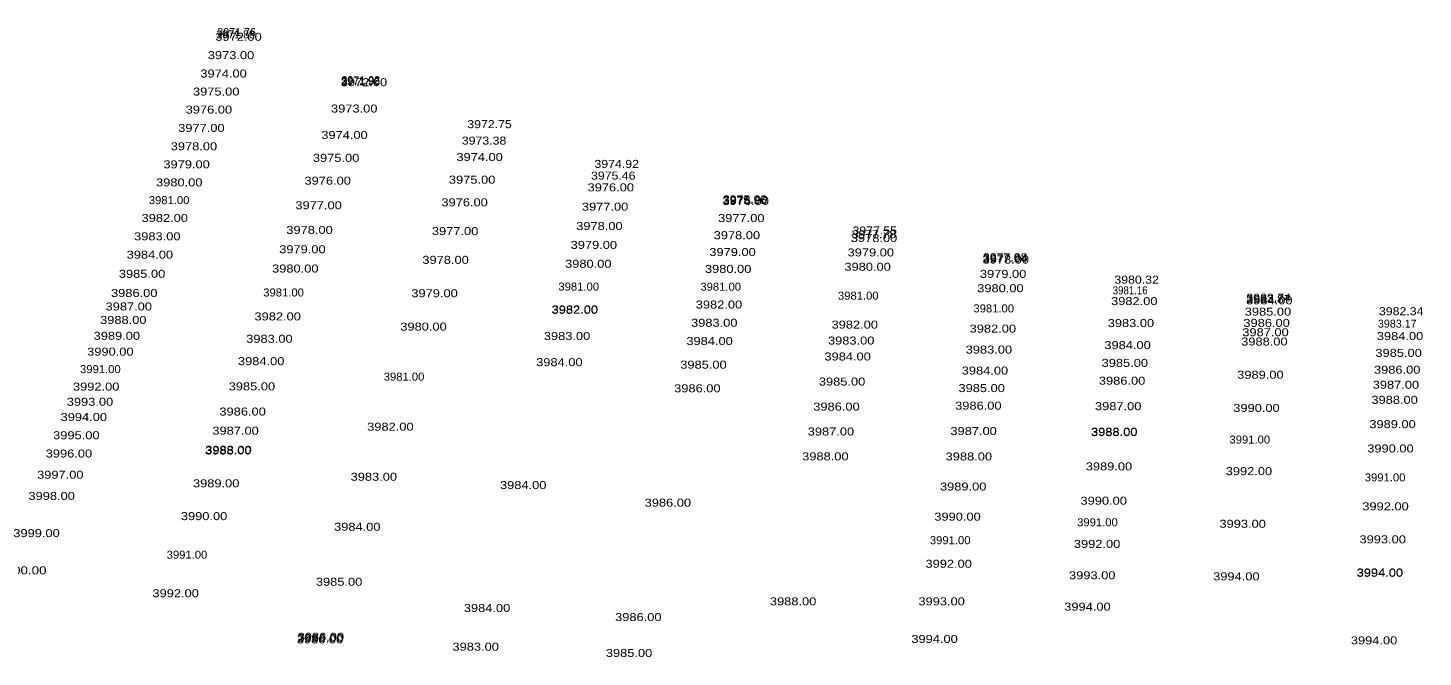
# Model space of a CAD drawing. Extents: x 49942 to 56479, y 47140 to 53283.
# Drawn here: x 51291 to 52163, y 50048 to 50441 of the extents above; entities that cross this region are included whole.
import ezdxf

# ---------------------------------------------------------------- set-up
doc = ezdxf.new("R2010")
doc.units = 0
doc.header["$LTSCALE"] = 2
doc.layers.add('29', color=7, linetype='Continuous')

msp = doc.modelspace()

# ---------------------------------------------------------------- texts
at = {"layer": '29'}
for s, width, p in [('3972.00', 1.2, (51408.123, 50433.343)), ('3973.00', 1.2, (51403.453, 50421.868)), ('3974.00', 1.2, (51398.784, 50410.394)), ('3975.00', 1.2, (51394.197, 50399.123)), ('3972.00', 1.2, (51486.503, 50404.978)), ('3976.00', 1.2, (51389.61, 50387.851)), ('3973.00', 1.2, (51480.438, 50388.516)), ('3977.00', 1.2, (51384.945, 50376.388)), ('3974.00', 1.2, (51474.341, 50371.968)), ('3972.75', 1.15, (51565.559, 50378.757)), ('3978.00', 1.2, (51380.279, 50364.924)), ('3973.38', 1.15, (51562.159, 50368.482)), ('3975.00', 1.2, (51469.09, 50357.718)), ('3974.00', 1.2, (51558.759, 50358.206)), ('3979.00', 1.2, (51375.69, 50353.647)), ('3975.46', 1.15, (51642.873, 50346.6)), ('3974.92', 1.15, (51645.029, 50353.931)), ('3980.00', 1.2, (51371.101, 50342.37)), ('3976.00', 1.2, (51463.84, 50343.467)), ('3975.00', 1.2, (51554.08, 50344.063)), ('3976.00', 1.2, (51640.717, 50339.269)), ('3981.00', 1.05, (51366.589, 50331.283)), ('3976.00', 1.2, (51549.4, 50329.92)), ('3976.00', 1.2, (51725.03, 50330.784)), ('3975.95', 1.15, (51725.158, 50331.281)), ('3975.90', 1.15, (51725.286, 50331.778)), ('3982.00', 1.2, (51362.048, 50320.124)), ('3977.00', 1.2, (51458.172, 50328.083)), ('3977.00', 1.2, (51637.167, 50327.197)), ('3977.00', 1.2, (51722.267, 50320.081)), ('3978.00', 1.2, (51452.493, 50312.671)), ('3977.00', 1.2, (51543.455, 50311.952)), ('3978.00', 1.2, (51633.616, 50315.125)), ('3977.55', 1.15, (51806.239, 50312.324)), ('3983.00', 1.2, (51357.391, 50308.68)), ('3979.00', 1.2, (51630.144, 50303.321)), ('3978.00', 1.2, (51719.505, 50309.378)), ('3978.00', 1.2, (51805.186, 50307.595)), ('3977.78', 1.15, (51805.713, 50309.959)), ('3984.00', 1.2, (51352.734, 50297.236)), ('3979.00', 1.2, (51448.051, 50300.613)), ('3978.00', 1.2, (51537.51, 50293.984)), ('3979.00', 1.2, (51716.788, 50298.85)), ('3979.00', 1.2, (51803.189, 50298.625)), ('3978.00', 1.2, (51887.528, 50294.152)), ('3977.94', 1.15, (51887.663, 50294.871)), ('3977.88', 1.15, (51887.798, 50295.59)), ('3985.00', 1.2, (51347.858, 50285.256)), ('3980.00', 1.2, (51443.608, 50288.555)), ('3980.00', 1.2, (51626.672, 50291.518)), ('3980.00', 1.2, (51714.07, 50288.321)), ('3980.00', 1.2, (51801.192, 50289.655)), ('3979.00', 1.2, (51885.847, 50285.2)), ('3981.00', 1.05, (51622.481, 50277.267)), ('3981.00', 1.05, (51711.197, 50277.19)), ('3980.00', 1.2, (51884.166, 50276.247)), ('3980.32', 1.15, (51969.872, 50281.595)), ('3986.00', 1.2, (51342.983, 50273.276)), ('3981.00', 1.05, (51438.096, 50273.595)), ('3979.00', 1.2, (51530.609, 50273.125)), ('3981.00', 1.05, (51797.168, 50271.585)), ('3982.00', 1.2, (51967.818, 50268.201)), ('3981.16', 0.9, (51968.852, 50274.945)), ('3984.00', 1.2, (52052.166, 50268.665)), ('3983.87', 1.15, (52052.267, 50269.51)), ('3983.74', 1.15, (52052.367, 50270.355)), ('3987.00', 1.2, (51339.555, 50264.852)), ('3982.00', 1.2, (51432.584, 50258.635)), ('3982.00', 1.2, (51618.211, 50262.749)), ('3982.00', 1.2, (51618.259, 50262.914)), ('3982.00', 1.2, (51618.289, 50263.016)), ('3982.00', 1.2, (51708.325, 50266.059)), ('3981.00', 1.05, (51881.796, 50263.628)), ('3985.00', 1.2, (52051.326, 50261.619)), ('3982.34', 1.15, (52135.193, 50261.883)), ('3988.00', 1.2, (51336.127, 50256.429)), ('3980.00', 1.2, (51523.707, 50252.266)), ('3983.00', 1.2, (51705.383, 50254.662)), ('3982.00', 1.2, (51793.144, 50253.515)), ('3982.00', 1.2, (51879.426, 50251.009)), ('3983.00', 1.2, (51965.712, 50254.469)), ('3986.00', 1.2, (52050.486, 50254.573)), ('3989.00', 1.2, (51332.097, 50246.527)), ('3983.00', 1.2, (51427.437, 50244.665)), ('3983.00', 1.2, (51613.402, 50246.399)), ('3984.00', 1.2, (51702.442, 50243.266)), ('3983.00', 1.2, (51790.927, 50243.558)), ('3988.00', 1.2, (52049.098, 50242.933)), ('3987.00', 1.2, (52049.792, 50248.753)), ('3984.00', 1.2, (52133.867, 50246.355)), ('3990.00', 1.2, (51328.068, 50236.626)), ('3984.00', 1.2, (51788.708, 50233.596)), ('3983.00', 1.2, (51876.966, 50237.906)), ('3984.00', 1.2, (51963.607, 50240.738)), ('3985.00', 1.2, (52132.969, 50235.846)), ('3991.00', 1.05, (51323.626, 50225.71)), ('3984.00', 1.2, (51422.285, 50230.68)), ('3984.00', 1.2, (51608.593, 50230.049)), ('3985.00', 1.2, (51698.629, 50228.492)), ('3984.00', 1.2, (51874.506, 50224.804)), ('3985.00', 1.2, (51961.9, 50229.605)), ('3986.00', 1.2, (52132.072, 50225.337)), ('3981.00', 1.05, (51513.36, 50220.995)), ('3985.00', 1.2, (51785.222, 50217.938)), ('3986.00', 1.2, (51960.192, 50218.471)), ('3989.00', 1.2, (52046.625, 50222.195)), ('3987.00', 1.2, (52131.269, 50215.931)), ('3992.00', 1.2, (51319.183, 50214.794)), ('3985.00', 1.2, (51416.485, 50214.941)), ('3986.00', 1.2, (51694.816, 50213.718)), ('3985.00', 1.2, (51872.449, 50213.851)), ('3988.00', 1.2, (52130.465, 50206.526)), ('3993.00', 1.2, (51315.318, 50205.296)), ('3986.00', 1.2, (51410.686, 50199.201)), ('3986.00', 1.2, (51781.735, 50202.28)), ('3986.00', 1.2, (51870.392, 50202.899)), ('3987.00', 1.2, (51957.751, 50202.548)), ('3990.00', 1.2, (52044.152, 50201.457)), ('3994.00', 1.2, (51311.453, 50195.799)), ('3982.00', 1.2, (51503.013, 50189.722)), ('3989.00', 1.2, (52129.167, 50191.329)), ('3995.00', 1.2, (51306.809, 50184.387)), ('3987.00', 1.2, (51406.281, 50187.246)), ('3987.00', 1.2, (51778.273, 50186.733)), ('3987.00', 1.2, (51867.411, 50187.026)), ('3988.00', 1.2, (51955.268, 50186.353)), ('3988.00', 1.2, (51955.288, 50186.489)), ('3988.00', 1.2, (51955.309, 50186.624)), ('3991.00', 1.05, (52041.797, 50181.706)), ('3996.00', 1.2, (51302.165, 50172.975)), ('3988.00', 1.2, (51401.723, 50174.874)), ('3988.00', 1.2, (51401.8, 50175.082)), ('3988.00', 1.2, (51401.877, 50175.291)), ('3990.00', 1.2, (52127.87, 50176.132)), ('3988.00', 1.2, (51774.811, 50171.185)), ('3988.00', 1.2, (51864.43, 50171.153)), ('3989.00', 1.2, (51951.983, 50164.93)), ('3997.00', 1.2, (51296.773, 50159.725)), ('3989.00', 1.2, (51394.167, 50154.365)), ('3983.00', 1.2, (51492.67, 50158.464)), ('3992.00', 1.2, (52039.442, 50161.955)), ('3991.00', 1.05, (52126.325, 50158.053)), ('3998.00', 1.2, (51291.381, 50146.475)), ('3984.00', 1.2, (51586.007, 50153.257)), ('3989.00', 1.2, (51860.898, 50152.343)), ('3986.00', 1.2, (51676.373, 50142.261)), ('3990.00', 1.2, (51948.698, 50143.508)), ('3992.00', 1.2, (52124.781, 50139.974)), ('3990.00', 1.2, (51386.61, 50133.856)), ('3990.00', 1.2, (51857.366, 50133.533)), ('3991.00', 1.05, (51946.629, 50130.013)), ('3993.00', 1.2, (52035.523, 50129.087)), ('3999.00', 1.2, (51281.921, 50123.228)), ('3984.00', 1.2, (51482.328, 50127.205)), ('3993.00', 1.2, (52123.02, 50119.353)), ('3991.00', 1.05, (51854.602, 50118.816)), ('3992.00', 1.2, (51944.559, 50116.519)), ('3991.00', 1.05, (51377.735, 50109.768)), ('3992.00', 1.2, (51851.838, 50104.098)), ('4000.00', 1.25, (51272.46, 50099.981)), ('3993.00', 1.2, (51941.551, 50096.899)), ('3994.00', 1.2, (52031.604, 50096.22)), ('3994.00', 1.2, (52121.235, 50098.447)), ('3994.00', 1.2, (52121.245, 50098.566)), ('3994.00', 1.2, (52121.255, 50098.685)), ('3992.00', 1.2, (51368.861, 50085.681)), ('3985.00', 1.2, (51470.959, 50092.846)), ('3984.00', 1.2, (51563.42, 50076.465)), ('3988.00', 1.2, (51754.642, 50080.612)), ('3993.00', 1.2, (51847.427, 50080.606)), ('3994.00', 1.2, (51938.543, 50077.279)), ('3986.00', 1.2, (51657.931, 50070.804)), ('3986.00', 1.2, (51459.591, 50058.486)), ('3986.00', 1.2, (51459.043, 50056.831)), ('3986.00', 1.2, (51459.317, 50057.659)), ('3983.00', 1.2, (51556.306, 50052.278)), ('3994.00', 1.2, (51843.015, 50057.114)), ('3994.00', 1.2, (52117.63, 50056.241)), ('3985.00', 1.2, (51652.137, 50048.354))]:
    msp.add_text(s, height=5, dxfattribs=dict(at, width=width)).set_placement(p)
for s, p in [('3971.88', (51408.728, 50434.83)), ('3971.76', (51409.333, 50436.318)), ('3971.96', (51486.734, 50405.604)), ('3971.92', (51486.965, 50406.23)), ('3983.17', (52134.53, 50254.119))]:
    msp.add_text(s, height=5, dxfattribs=at).set_placement(p)

doc.saveas('drawing.dxf')
